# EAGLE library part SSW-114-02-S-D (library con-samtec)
THROUGH-HOLE .025" SQ POST SOCKET Source: Samtec SSW.pdf
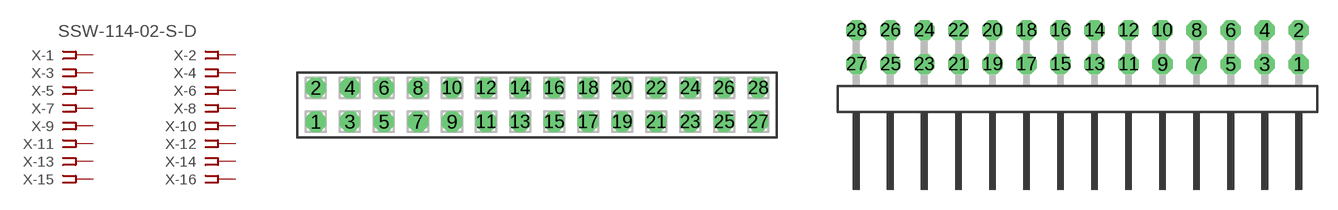
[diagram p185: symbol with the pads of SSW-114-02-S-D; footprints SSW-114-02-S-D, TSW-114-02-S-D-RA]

Designator prefix X; gates -1=FPINV -2=FPIN -3=FPIN -4=FPIN -5=FPIN -6=FPIN -7=FPIN -8=FPIN -9=FPIN -10=FPIN -11=FPIN -12=FPIN -13=FPIN -14=FPIN -15=FPIN -16=FPIN -17=FPIN -18=FPIN -19=FPIN -20=FPIN -21=FPIN -22=FPIN -23=FPIN -24=FPIN -25=FPIN -26=FPIN -27=FPIN -28=FPIN

## SSW-114-02-S-D (MPN: SSW-114-02-S-D; OC_FARNELL: unknown; OC_NEWARK: 11P9547)  [SSW-114-02-S-D]
1  -1:1  pas
2  -2:1  pas
3  -3:1  pas
4  -4:1  pas
5  -5:1  pas
6  -6:1  pas
7  -7:1  pas
8  -8:1  pas
9  -9:1  pas
10  -10:1  pas
11  -11:1  pas
12  -12:1  pas
13  -13:1  pas
14  -14:1  pas
15  -15:1  pas
16  -16:1  pas
17  -17:1  pas
18  -18:1  pas
19  -19:1  pas
20  -20:1  pas
21  -21:1  pas
22  -22:1  pas
23  -23:1  pas
24  -24:1  pas
25  -25:1  pas
26  -26:1  pas
27  -27:1  pas
28  -28:1  pas

## SSW-114-02-S-D-RA (MPN: SSW-114-02-S-D-RA; OC_FARNELL: unknown; OC_NEWARK: 11P9548)  [TSW-114-02-S-D-RA]
Pads as for SSW-114-02-S-D

## Footprint SSW-114-02-S-D (pad centres in mm)
THROUGH-HOLE .025" SQ POST SOCKET Source: Samtec SSW.pdf
drill 1 pad 1.5 octagon: 1 -16.51,-1.27; 2 -16.51,1.27; 3 -13.97,-1.27; 4 -13.97,1.27; 5 -11.43,-1.27; 6 -11.43,1.27; 7 -8.89,-1.27; 8 -8.89,1.27; 9 -6.35,-1.27; 10 -6.35,1.27; 11 -3.81,-1.27; 12 -3.81,1.27; 13 -1.27,-1.27; 14 -1.27,1.27; 15 1.27,-1.27; 16 1.27,1.27; 17 3.81,-1.27; 18 3.81,1.27; 19 6.35,-1.27; 20 6.35,1.27; 21 8.89,-1.27; 22 8.89,1.27; 23 11.43,-1.27; 24 11.43,1.27; 25 13.97,-1.27; 26 13.97,1.27; 27 16.51,-1.27; 28 16.51,1.27

## Footprint TSW-114-02-S-D-RA (pad centres in mm)
THROUGH-HOLE .025" SQ POST HEADER Source: Samtec TSW.pdf
drill 1 pad 1.5 octagon: 1 16.51,1.524; 2 16.51,4.064; 3 13.97,1.524; 4 13.97,4.064; 5 11.43,1.524; 6 11.43,4.064; 7 8.89,1.524; 8 8.89,4.064; 9 6.35,1.524; 10 6.35,4.064; 11 3.81,1.524; 12 3.81,4.064; 13 1.27,1.524; 14 1.27,4.064; 15 -1.27,1.524; 16 -1.27,4.064; 17 -3.81,1.524; 18 -3.81,4.064; 19 -6.35,1.524; 20 -6.35,4.064; 21 -8.89,1.524; 22 -8.89,4.064; 23 -11.43,1.524; 24 -11.43,4.064; 25 -13.97,1.524; 26 -13.97,4.064; 27 -16.51,1.524; 28 -16.51,4.064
